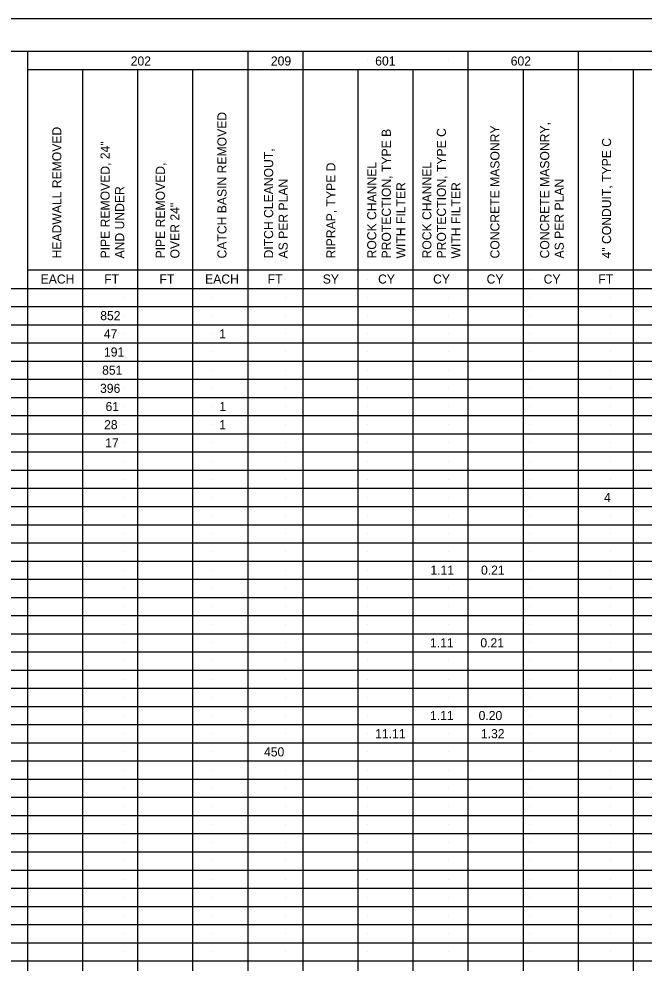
# Model space of a CAD drawing. Extents: x 2073163.9 to 2073197.9, y 634076.5 to 634098.5.
# Drawn here: x 2073171.21 to 2073180.84, y 634084 to 634098.55 of the extents above; entities that cross this region are included whole.
import ezdxf

# ---------------------------------------------------------------- set-up
doc = ezdxf.new("R2010")
doc.units = 0
for name, color, linetype in [('SH_Border', 7, 'Continuous'), ('SH_Cut_Line', 7, 'Continuous'), ('SH_Data', 7, 'Continuous'), ('SH_Text', 7, 'Continuous')]:
    doc.layers.add(name, color=color, linetype=linetype)

msp = doc.modelspace()

# ---------------------------------------------------------------- linework, layer by layer
at = {"layer": 'SH_Border'}
msp.add_lwpolyline([(2073165.446, 634098.05), (2073197.446, 634098.05), (2073197.446, 634077.05), (2073165.446, 634077.05)], close=True, dxfattribs=at)
at = {"layer": 'SH_Cut_Line'}
msp.add_lwpolyline([(2073163.946, 634076.55), (2073197.946, 634076.55), (2073197.946, 634098.55), (2073163.946, 634098.55)], close=True, dxfattribs=at)
at = {"layer": 'SH_Data'}
for p, q in [((2073171.345, 634077.05), (2073171.345, 634098.05)), ((2073175.321, 634097.91), (2073175.321, 634097.91)), ((2073176.571, 634097.91), (2073176.571, 634097.91)), ((2073177.821, 634097.91), (2073177.821, 634097.91)), ((2073179.071, 634097.91), (2073179.071, 634097.91)), ((2073180.321, 634097.91), (2073180.321, 634097.91)), ((2073171.345, 634097.77), (2073195.946, 634097.77)), ((2073171.345, 634094.682), (2073195.945, 634094.682)), ((2073175.321, 634094.538), (2073175.321, 634094.538)), ((2073176.571, 634094.538), (2073176.571, 634094.538)), ((2073177.821, 634094.538), (2073177.821, 634094.538)), ((2073179.071, 634094.538), (2073179.071, 634094.538)), ((2073180.321, 634094.538), (2073180.321, 634094.538)), ((2073165.446, 634094.398), (2073195.946, 634094.398)), ((2073172.821, 634094.258), (2073172.821, 634094.258)), ((2073174.196, 634094.258), (2073174.196, 634094.258)), ((2073175.321, 634094.258), (2073175.321, 634094.258)), ((2073176.571, 634094.258), (2073176.571, 634094.258)), ((2073177.821, 634094.258), (2073177.821, 634094.258)), ((2073179.071, 634094.258), (2073179.071, 634094.258)), ((2073180.321, 634094.258), (2073180.321, 634094.258)), ((2073165.44, 634094.118), (2073195.948, 634094.118)), ((2073172.821, 634093.978), (2073172.821, 634093.978)), ((2073174.196, 634093.978), (2073174.196, 634093.978)), ((2073175.321, 634093.978), (2073175.321, 634093.978)), ((2073176.571, 634093.978), (2073176.571, 634093.978)), ((2073177.821, 634093.978), (2073177.821, 634093.978)), ((2073179.071, 634093.978), (2073179.071, 634093.978)), ((2073180.321, 634093.978), (2073180.321, 634093.978)), ((2073165.45, 634093.838), (2073195.947, 634093.838)), ((2073172.821, 634093.698), (2073172.821, 634093.698)), ((2073174.196, 634093.698), (2073174.196, 634093.698)), ((2073175.321, 634093.698), (2073175.321, 634093.698)), ((2073176.571, 634093.698), (2073176.571, 634093.698)), ((2073177.821, 634093.698), (2073177.821, 634093.698)), ((2073179.071, 634093.698), (2073179.071, 634093.698)), ((2073180.321, 634093.698), (2073180.321, 634093.698)), ((2073165.45, 634093.558), (2073195.947, 634093.558)), ((2073172.821, 634093.418), (2073172.821, 634093.418)), ((2073174.196, 634093.418), (2073174.196, 634093.418)), ((2073175.321, 634093.418), (2073175.321, 634093.418)), ((2073176.571, 634093.418), (2073176.571, 634093.418)), ((2073177.821, 634093.418), (2073177.821, 634093.418)), ((2073179.071, 634093.418), (2073179.071, 634093.418)), ((2073180.321, 634093.418), (2073180.321, 634093.418)), ((2073165.447, 634093.278), (2073195.949, 634093.278)), ((2073172.821, 634093.138), (2073172.821, 634093.138)), ((2073174.196, 634093.138), (2073174.196, 634093.138)), ((2073175.321, 634093.138), (2073175.321, 634093.138)), ((2073176.571, 634093.138), (2073176.571, 634093.138)), ((2073177.821, 634093.138), (2073177.821, 634093.138)), ((2073179.071, 634093.138), (2073179.071, 634093.138)), ((2073180.321, 634093.138), (2073180.321, 634093.138)), ((2073165.444, 634092.998), (2073195.947, 634092.998)), ((2073172.821, 634092.858), (2073172.821, 634092.858)), ((2073174.196, 634092.858), (2073174.196, 634092.858)), ((2073175.321, 634092.858), (2073175.321, 634092.858)), ((2073176.571, 634092.858), (2073176.571, 634092.858)), ((2073177.821, 634092.858), (2073177.821, 634092.858)), ((2073179.071, 634092.858), (2073179.071, 634092.858)), ((2073180.321, 634092.858), (2073180.321, 634092.858)), ((2073165.454, 634092.718), (2073195.947, 634092.718)), ((2073172.821, 634092.578), (2073172.821, 634092.578)), ((2073174.196, 634092.578), (2073174.196, 634092.578)), ((2073175.321, 634092.578), (2073175.321, 634092.578)), ((2073176.571, 634092.578), (2073176.571, 634092.578)), ((2073177.821, 634092.578), (2073177.821, 634092.578)), ((2073179.071, 634092.578), (2073179.071, 634092.578)), ((2073180.321, 634092.578), (2073180.321, 634092.578)), ((2073165.45, 634092.438), (2073195.943, 634092.438)), ((2073172.821, 634092.298), (2073172.821, 634092.298)), ((2073174.196, 634092.298), (2073174.196, 634092.298)), ((2073175.321, 634092.298), (2073175.321, 634092.298)), ((2073176.571, 634092.298), (2073176.571, 634092.298)), ((2073177.821, 634092.298), (2073177.821, 634092.298)), ((2073179.071, 634092.298), (2073179.071, 634092.298)), ((2073180.321, 634092.298), (2073180.321, 634092.298)), ((2073165.448, 634092.158), (2073195.943, 634092.158)), ((2073172.821, 634092.018), (2073172.821, 634092.018)), ((2073174.196, 634092.018), (2073174.196, 634092.018)), ((2073175.321, 634092.018), (2073175.321, 634092.018)), ((2073176.571, 634092.018), (2073176.571, 634092.018)), ((2073177.821, 634092.018), (2073177.821, 634092.018)), ((2073179.071, 634092.018), (2073179.071, 634092.018)), ((2073180.321, 634092.018), (2073180.321, 634092.018)), ((2073165.448, 634091.878), (2073195.943, 634091.878)), ((2073172.821, 634091.738), (2073172.821, 634091.738)), ((2073174.196, 634091.738), (2073174.196, 634091.738)), ((2073175.321, 634091.738), (2073175.321, 634091.738)), ((2073176.571, 634091.738), (2073176.571, 634091.738)), ((2073177.821, 634091.738), (2073177.821, 634091.738)), ((2073179.071, 634091.738), (2073179.071, 634091.738)), ((2073180.321, 634091.738), (2073180.321, 634091.738)), ((2073165.448, 634091.598), (2073195.948, 634091.598)), ((2073172.821, 634091.458), (2073172.821, 634091.458)), ((2073174.196, 634091.458), (2073174.196, 634091.458)), ((2073175.321, 634091.458), (2073175.321, 634091.458)), ((2073176.571, 634091.458), (2073176.571, 634091.458)), ((2073177.821, 634091.458), (2073177.821, 634091.458)), ((2073179.071, 634091.458), (2073179.071, 634091.458)), ((2073180.321, 634091.458), (2073180.321, 634091.458)), ((2073165.451, 634091.318), (2073195.939, 634091.318)), ((2073165.451, 634091.318), (2073195.944, 634091.318)), ((2073172.821, 634091.178), (2073172.821, 634091.178)), ((2073174.196, 634091.178), (2073174.196, 634091.178)), ((2073175.321, 634091.178), (2073175.321, 634091.178)), ((2073176.571, 634091.178), (2073176.571, 634091.178)), ((2073177.821, 634091.178), (2073177.821, 634091.178)), ((2073179.071, 634091.178), (2073179.071, 634091.178)), ((2073180.321, 634091.178), (2073180.321, 634091.178)), ((2073165.448, 634091.038), (2073195.944, 634091.038)), ((2073172.821, 634090.898), (2073172.821, 634090.898)), ((2073174.196, 634090.898), (2073174.196, 634090.898)), ((2073175.321, 634090.898), (2073175.321, 634090.898)), ((2073176.571, 634090.898), (2073176.571, 634090.898)), ((2073177.821, 634090.898), (2073177.821, 634090.898)), ((2073179.071, 634090.898), (2073179.071, 634090.898)), ((2073180.321, 634090.898), (2073180.321, 634090.898)), ((2073165.445, 634090.758), (2073195.942, 634090.758)), ((2073172.821, 634090.618), (2073172.821, 634090.618)), ((2073174.196, 634090.618), (2073174.196, 634090.618)), ((2073175.321, 634090.618), (2073175.321, 634090.618)), ((2073176.571, 634090.618), (2073176.571, 634090.618)), ((2073177.821, 634090.618), (2073177.821, 634090.618)), ((2073179.071, 634090.618), (2073179.071, 634090.618)), ((2073180.321, 634090.618), (2073180.321, 634090.618)), ((2073165.442, 634090.478), (2073195.946, 634090.478)), ((2073172.821, 634090.338), (2073172.821, 634090.338)), ((2073174.196, 634090.338), (2073174.196, 634090.338)), ((2073175.321, 634090.338), (2073175.321, 634090.338)), ((2073176.571, 634090.338), (2073176.571, 634090.338)), ((2073177.821, 634090.338), (2073177.821, 634090.338)), ((2073179.071, 634090.338), (2073179.071, 634090.338)), ((2073180.321, 634090.338), (2073180.321, 634090.338)), ((2073165.442, 634090.198), (2073195.946, 634090.198)), ((2073172.821, 634090.058), (2073172.821, 634090.058)), ((2073174.196, 634090.058), (2073174.196, 634090.058)), ((2073175.321, 634090.058), (2073175.321, 634090.058)), ((2073176.571, 634090.058), (2073176.571, 634090.058)), ((2073177.821, 634090.058), (2073177.821, 634090.058)), ((2073179.071, 634090.058), (2073179.071, 634090.058)), ((2073180.321, 634090.058), (2073180.321, 634090.058)), ((2073165.446, 634089.918), (2073195.946, 634089.918)), ((2073172.821, 634089.778), (2073172.821, 634089.778)), ((2073174.196, 634089.778), (2073174.196, 634089.778)), ((2073175.321, 634089.778), (2073175.321, 634089.778)), ((2073176.571, 634089.778), (2073176.571, 634089.778)), ((2073177.821, 634089.778), (2073177.821, 634089.778)), ((2073179.071, 634089.778), (2073179.071, 634089.778)), ((2073180.321, 634089.778), (2073180.321, 634089.778)), ((2073165.446, 634089.638), (2073195.946, 634089.638)), ((2073172.821, 634089.498), (2073172.821, 634089.498)), ((2073174.196, 634089.498), (2073174.196, 634089.498)), ((2073175.321, 634089.498), (2073175.321, 634089.498)), ((2073176.571, 634089.498), (2073176.571, 634089.498)), ((2073177.821, 634089.498), (2073177.821, 634089.498)), ((2073179.071, 634089.498), (2073179.071, 634089.498)), ((2073180.321, 634089.498), (2073180.321, 634089.498)), ((2073165.446, 634089.358), (2073195.946, 634089.358)), ((2073172.821, 634089.218), (2073172.821, 634089.218)), ((2073174.196, 634089.218), (2073174.196, 634089.218)), ((2073175.321, 634089.218), (2073175.321, 634089.218)), ((2073176.571, 634089.218), (2073176.571, 634089.218)), ((2073177.821, 634089.218), (2073177.821, 634089.218)), ((2073179.071, 634089.218), (2073179.071, 634089.218)), ((2073180.321, 634089.218), (2073180.321, 634089.218)), ((2073165.446, 634089.078), (2073195.946, 634089.078)), ((2073172.821, 634088.938), (2073172.821, 634088.938)), ((2073174.196, 634088.938), (2073174.196, 634088.938)), ((2073175.321, 634088.938), (2073175.321, 634088.938)), ((2073176.571, 634088.938), (2073176.571, 634088.938)), ((2073177.821, 634088.938), (2073177.821, 634088.938)), ((2073179.071, 634088.938), (2073179.071, 634088.938)), ((2073180.321, 634088.938), (2073180.321, 634088.938)), ((2073165.446, 634088.798), (2073195.946, 634088.798)), ((2073172.821, 634088.658), (2073172.821, 634088.658)), ((2073174.196, 634088.658), (2073174.196, 634088.658)), ((2073175.321, 634088.658), (2073175.321, 634088.658)), ((2073176.571, 634088.658), (2073176.571, 634088.658)), ((2073177.821, 634088.658), (2073177.821, 634088.658)), ((2073179.071, 634088.658), (2073179.071, 634088.658)), ((2073180.321, 634088.658), (2073180.321, 634088.658)), ((2073165.446, 634088.518), (2073195.946, 634088.518)), ((2073172.821, 634088.378), (2073172.821, 634088.378)), ((2073174.196, 634088.378), (2073174.196, 634088.378)), ((2073175.321, 634088.378), (2073175.321, 634088.378)), ((2073176.571, 634088.378), (2073176.571, 634088.378)), ((2073177.821, 634088.378), (2073177.821, 634088.378)), ((2073179.071, 634088.378), (2073179.071, 634088.378)), ((2073180.321, 634088.378), (2073180.321, 634088.378)), ((2073165.446, 634088.238), (2073195.946, 634088.238)), ((2073172.821, 634088.098), (2073172.821, 634088.098)), ((2073174.196, 634088.098), (2073174.196, 634088.098)), ((2073175.321, 634088.098), (2073175.321, 634088.098)), ((2073176.571, 634088.098), (2073176.571, 634088.098)), ((2073177.821, 634088.098), (2073177.821, 634088.098)), ((2073179.071, 634088.098), (2073179.071, 634088.098)), ((2073180.321, 634088.098), (2073180.321, 634088.098)), ((2073165.446, 634087.958), (2073195.946, 634087.958)), ((2073172.821, 634087.818), (2073172.821, 634087.818)), ((2073174.196, 634087.818), (2073174.196, 634087.818)), ((2073175.321, 634087.818), (2073175.321, 634087.818)), ((2073176.571, 634087.818), (2073176.571, 634087.818)), ((2073177.821, 634087.818), (2073177.821, 634087.818)), ((2073179.071, 634087.818), (2073179.071, 634087.818)), ((2073180.321, 634087.818), (2073180.321, 634087.818)), ((2073165.446, 634087.678), (2073195.946, 634087.678)), ((2073172.821, 634087.538), (2073172.821, 634087.538)), ((2073174.196, 634087.538), (2073174.196, 634087.538)), ((2073175.321, 634087.538), (2073175.321, 634087.538)), ((2073176.571, 634087.538), (2073176.571, 634087.538)), ((2073177.821, 634087.538), (2073177.821, 634087.538)), ((2073179.071, 634087.538), (2073179.071, 634087.538)), ((2073180.321, 634087.538), (2073180.321, 634087.538)), ((2073165.446, 634087.398), (2073195.946, 634087.398)), ((2073172.821, 634087.258), (2073172.821, 634087.258)), ((2073174.196, 634087.258), (2073174.196, 634087.258)), ((2073175.321, 634087.258), (2073175.321, 634087.258)), ((2073176.571, 634087.258), (2073176.571, 634087.258)), ((2073177.821, 634087.258), (2073177.821, 634087.258)), ((2073179.071, 634087.258), (2073179.071, 634087.258)), ((2073180.321, 634087.258), (2073180.321, 634087.258)), ((2073165.446, 634087.118), (2073195.946, 634087.118)), ((2073172.821, 634086.978), (2073172.821, 634086.978)), ((2073174.196, 634086.978), (2073174.196, 634086.978)), ((2073175.321, 634086.978), (2073175.321, 634086.978)), ((2073176.571, 634086.978), (2073176.571, 634086.978)), ((2073177.821, 634086.978), (2073177.821, 634086.978)), ((2073179.071, 634086.978), (2073179.071, 634086.978)), ((2073180.321, 634086.978), (2073180.321, 634086.978)), ((2073165.446, 634086.838), (2073195.946, 634086.838)), ((2073172.821, 634086.698), (2073172.821, 634086.698)), ((2073174.196, 634086.698), (2073174.196, 634086.698)), ((2073175.321, 634086.698), (2073175.321, 634086.698)), ((2073176.571, 634086.698), (2073176.571, 634086.698)), ((2073177.821, 634086.698), (2073177.821, 634086.698)), ((2073179.071, 634086.698), (2073179.071, 634086.698)), ((2073180.321, 634086.698), (2073180.321, 634086.698)), ((2073165.446, 634086.558), (2073195.946, 634086.558)), ((2073172.821, 634086.418), (2073172.821, 634086.418)), ((2073174.196, 634086.418), (2073174.196, 634086.418)), ((2073175.321, 634086.418), (2073175.321, 634086.418)), ((2073176.571, 634086.418), (2073176.571, 634086.418)), ((2073177.821, 634086.418), (2073177.821, 634086.418)), ((2073179.071, 634086.418), (2073179.071, 634086.418)), ((2073180.321, 634086.418), (2073180.321, 634086.418)), ((2073165.446, 634086.278), (2073195.946, 634086.278)), ((2073165.446, 634085.998), (2073195.946, 634085.998)), ((2073172.821, 634086.138), (2073172.821, 634086.138)), ((2073174.196, 634086.138), (2073174.196, 634086.138)), ((2073175.321, 634086.138), (2073175.321, 634086.138)), ((2073176.571, 634086.138), (2073176.571, 634086.138)), ((2073177.821, 634086.138), (2073177.821, 634086.138)), ((2073179.071, 634086.138), (2073179.071, 634086.138)), ((2073180.321, 634086.138), (2073180.321, 634086.138)), ((2073172.821, 634085.858), (2073172.821, 634085.858)), ((2073174.196, 634085.858), (2073174.196, 634085.858)), ((2073175.321, 634085.858), (2073175.321, 634085.858)), ((2073176.571, 634085.858), (2073176.571, 634085.858)), ((2073177.821, 634085.858), (2073177.821, 634085.858)), ((2073179.071, 634085.858), (2073179.071, 634085.858)), ((2073180.321, 634085.858), (2073180.321, 634085.858)), ((2073165.446, 634085.718), (2073195.946, 634085.718)), ((2073172.821, 634085.578), (2073172.821, 634085.578)), ((2073174.196, 634085.578), (2073174.196, 634085.578)), ((2073175.321, 634085.578), (2073175.321, 634085.578)), ((2073176.571, 634085.578), (2073176.571, 634085.578)), ((2073177.821, 634085.578), (2073177.821, 634085.578)), ((2073179.071, 634085.578), (2073179.071, 634085.578)), ((2073180.321, 634085.578), (2073180.321, 634085.578)), ((2073165.446, 634085.438), (2073195.946, 634085.438)), ((2073172.821, 634085.298), (2073172.821, 634085.298)), ((2073174.196, 634085.298), (2073174.196, 634085.298)), ((2073175.321, 634085.298), (2073175.321, 634085.298)), ((2073176.571, 634085.298), (2073176.571, 634085.298)), ((2073177.821, 634085.298), (2073177.821, 634085.298)), ((2073179.071, 634085.298), (2073179.071, 634085.298)), ((2073180.321, 634085.298), (2073180.321, 634085.298)), ((2073165.446, 634085.158), (2073195.946, 634085.158)), ((2073172.821, 634085.018), (2073172.821, 634085.018)), ((2073174.196, 634085.018), (2073174.196, 634085.018)), ((2073175.321, 634085.018), (2073175.321, 634085.018)), ((2073176.571, 634085.018), (2073176.571, 634085.018)), ((2073177.821, 634085.018), (2073177.821, 634085.018)), ((2073179.071, 634085.018), (2073179.071, 634085.018)), ((2073180.321, 634085.018), (2073180.321, 634085.018)), ((2073165.446, 634084.878), (2073195.946, 634084.878)), ((2073172.821, 634084.738), (2073172.821, 634084.738)), ((2073174.196, 634084.738), (2073174.196, 634084.738)), ((2073175.321, 634084.738), (2073175.321, 634084.738)), ((2073176.571, 634084.738), (2073176.571, 634084.738)), ((2073177.821, 634084.738), (2073177.821, 634084.738)), ((2073179.071, 634084.738), (2073179.071, 634084.738)), ((2073180.321, 634084.738), (2073180.321, 634084.738)), ((2073165.446, 634084.598), (2073195.946, 634084.598)), ((2073172.821, 634084.458), (2073172.821, 634084.458)), ((2073174.196, 634084.458), (2073174.196, 634084.458)), ((2073175.321, 634084.458), (2073175.321, 634084.458)), ((2073176.571, 634084.458), (2073176.571, 634084.458)), ((2073177.821, 634084.458), (2073177.821, 634084.458)), ((2073179.071, 634084.458), (2073179.071, 634084.458)), ((2073180.321, 634084.458), (2073180.321, 634084.458)), ((2073165.446, 634084.318), (2073195.946, 634084.318)), ((2073172.821, 634084.178), (2073172.821, 634084.178)), ((2073174.196, 634084.178), (2073174.196, 634084.178)), ((2073175.321, 634084.178), (2073175.321, 634084.178)), ((2073176.571, 634084.178), (2073176.571, 634084.178)), ((2073177.821, 634084.178), (2073177.821, 634084.178)), ((2073179.071, 634084.178), (2073179.071, 634084.178)), ((2073180.321, 634084.178), (2073180.321, 634084.178)), ((2073165.446, 634084.038), (2073195.946, 634084.038))]:
    msp.add_line(p, q, dxfattribs=at)
at = {"layer": 'SH_Text'}
for p, q in [((2073174.738, 634077.05), (2073174.738, 634098.05)), ((2073175.587, 634077.05), (2073175.587, 634098.05)), ((2073178.131, 634077.05), (2073178.131, 634098.05)), ((2073179.828, 634077.05), (2073179.828, 634098.05)), ((2073172.193, 634077.05), (2073172.193, 634097.77)), ((2073173.042, 634077.05), (2073173.042, 634097.77)), ((2073173.89, 634077.05), (2073173.89, 634097.77)), ((2073176.435, 634077.05), (2073176.435, 634097.77)), ((2073177.283, 634077.05), (2073177.283, 634097.77)), ((2073178.98, 634077.05), (2073178.98, 634097.77)), ((2073180.676, 634077.05), (2073180.676, 634097.77))]:
    msp.add_line(p, q, dxfattribs=at)

# ---------------------------------------------------------------- texts
for s, rotation, p in [('202', 0.0001, (2073172.931, 634097.831)), ('209', 0.0001, (2073175.09, 634097.831)), ('601', 0.0001, (2073176.697, 634097.831)), ('602', 0.0001, (2073178.785, 634097.831)), ('CATCH BASIN REMOVED', 90.0001, (2073174.406, 634094.859)), ('CONCRETE MASONRY,', 90.0001, (2073179.378, 634094.859)), ('HEADWALL REMOVED', 90.0001, (2073171.862, 634094.859)), ('PROTECTION, TYPE B', 90.0001, (2073176.938, 634094.859)), ('PROTECTION, TYPE C', 90.0001, (2073177.787, 634094.859)), ('CONCRETE MASONRY', 90.0001, (2073178.611, 634094.859)), ('PIPE REMOVED, 24"', 90.0001, (2073172.606, 634094.859)), ('4" CONDUIT, TYPE C', 90.0001, (2073180.331, 634094.859)), ('DITCH CLEANOUT,', 90.0001, (2073175.125, 634094.859)), ('RIPRAP, TYPE D', 90.0001, (2073176.085, 634094.859)), ('ROCK CHANNEL', 90.0001, (2073176.714, 634094.859)), ('ROCK CHANNEL', 90.0001, (2073177.563, 634094.859)), ('PIPE REMOVED, ', 90.0001, (2073173.457, 634094.859)), ('AS PER PLAN', 90.0001, (2073175.349, 634094.859)), ('AS PER PLAN', 90.0001, (2073179.602, 634094.859)), ('AND UNDER', 90.0001, (2073172.83, 634094.859)), ('WITH FILTER', 90.0001, (2073177.162, 634094.859)), ('WITH FILTER', 90.0001, (2073178.011, 634094.859)), ('OVER 24"', 90.0001, (2073173.681, 634094.859)), ('EACH', 0.0001, (2073171.543, 634094.472)), ('FT', 0.0001, (2073172.523, 634094.472)), ('FT', 0.0001, (2073173.374, 634094.472)), ('EACH', 0.0001, (2073174.077, 634094.472)), ('FT', 0.0001, (2073175.041, 634094.472)), ('SY', 0.0001, (2073175.889, 634094.472)), ('CY', 0.0001, (2073176.741, 634094.472)), ('CY', 0.0001, (2073177.589, 634094.472)), ('CY', 0.0001, (2073178.413, 634094.472)), ('CY', 0.0001, (2073179.292, 634094.472)), ('FT', 0.0001, (2073180.135, 634094.472)), ('852', 0.0001, (2073172.461, 634093.908)), ('47', 0.0001, (2073172.517, 634093.628)), ('1', 0.0001, (2073174.293, 634093.628)), ('191', 0.0001, (2073172.519, 634093.348)), ('851', 0.0001, (2073172.49, 634093.068)), ('396', 0.0001, (2073172.458, 634092.788)), ('61', 0.0001, (2073172.543, 634092.508)), ('1', 0.0001, (2073174.296, 634092.508)), ('28', 0.0001, (2073172.52, 634092.228)), ('1', 0.0001, (2073174.294, 634092.228)), ('17', 0.0001, (2073172.538, 634091.948)), ('4', 0.0001, (2073180.223, 634091.108)), ('1.11', 0.0001, (2073177.547, 634089.988)), ('0.21', 0.0001, (2073178.327, 634089.988)), ('1.11', 0.0001, (2073177.541, 634088.868)), ('0.21', 0.0001, (2073178.317, 634088.868)), ('1.11', 0.0001, (2073177.541, 634087.748)), ('0.20', 0.0001, (2073178.29, 634087.748)), ('11.11', 0.0001, (2073176.696, 634087.468)), ('1.32', 0.0001, (2073178.325, 634087.468)), ('450', 0.0001, (2073174.984, 634087.188))]:
    msp.add_text(s, height=0.14, rotation=rotation, dxfattribs=at).set_placement(p)

doc.saveas('drawing.dxf')
